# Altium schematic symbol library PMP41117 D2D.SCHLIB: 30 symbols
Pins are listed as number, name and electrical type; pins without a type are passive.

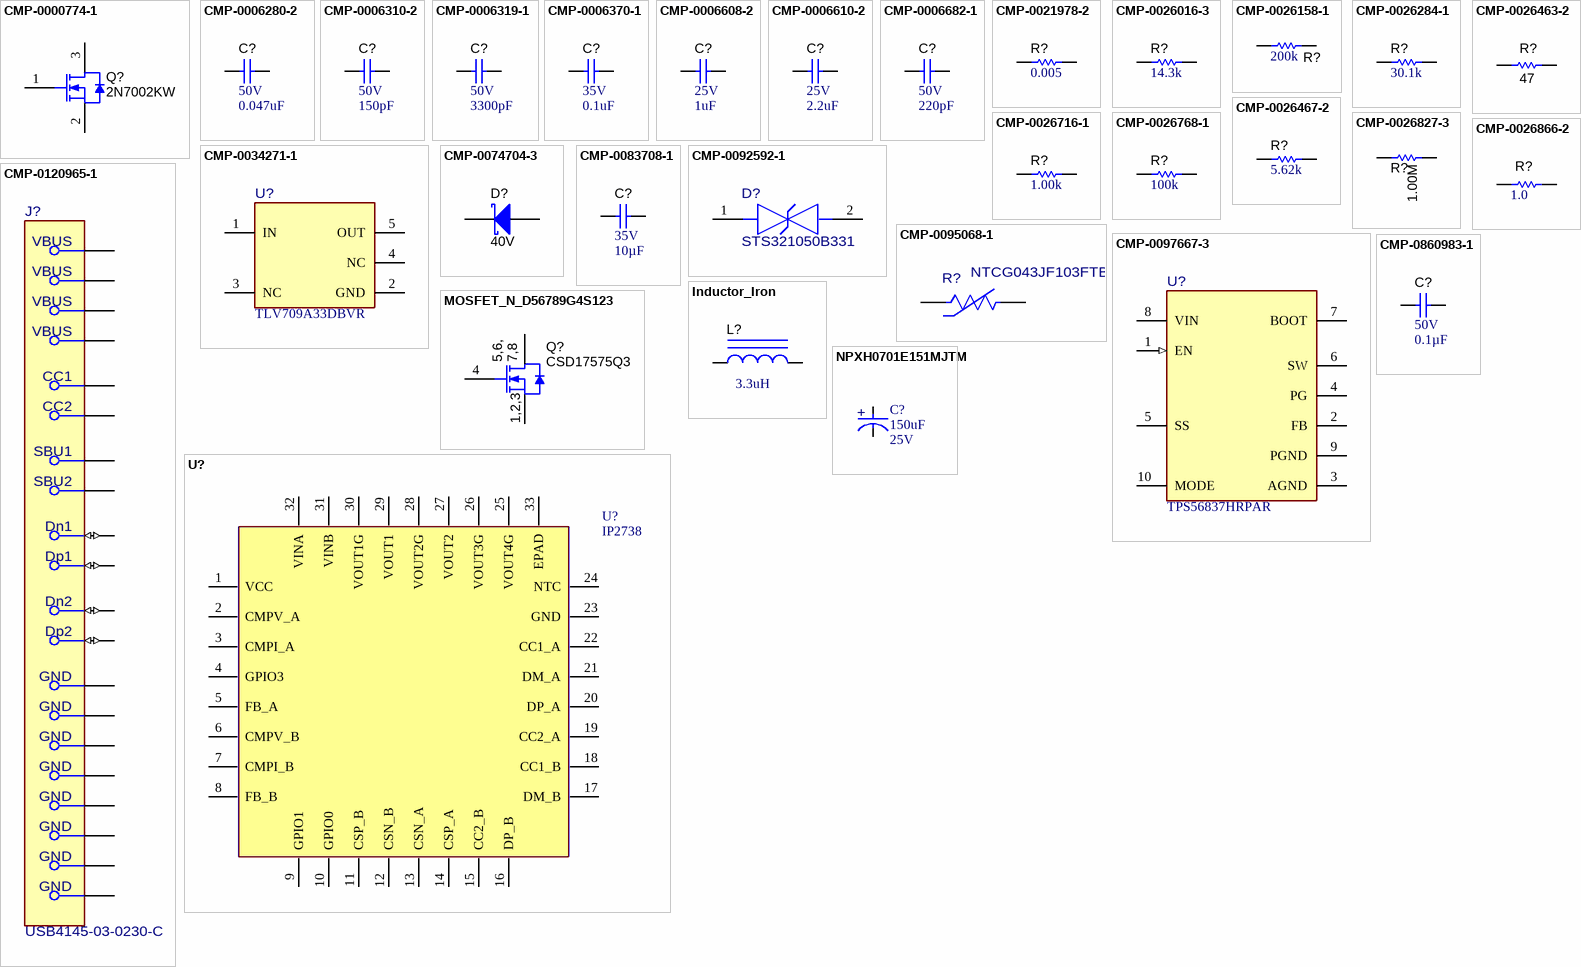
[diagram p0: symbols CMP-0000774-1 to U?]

## CMP-0000774-1
designator Q?, comment 2N7002KW
MOSFET, N-CH, 60 V, 0.31 A, SOT-323; Alternate Manufacturer: None; Manufacturer: Fairchild Semiconductor; SizeZ_mm: 1.1; ChType: N; Value1: 1; VdsMax_V: 60V; SizeX_mm: 2.2; Vgs_V: 2.1V; Value: 60V; Rdson45_ohm: 1.6; SizeArea_mm2: 4.84; AEC Category: Q101; IdsMax_A: 310mA; SizeAreaWB_mm2: 10.24; U/M: EA
footprint SOT-323 (Diodes Inc recommended land pattern.  2016-02-24)
pins: 1 G, 2 S, 3 D

## CMP-0006280-2
designator C?, comment VDC_V: 50V  ValueDisplayed: 0.047uF  (hidden comment: C1005X5R1H473K050BB)
CAP, CERM, 0.047 uF, 50 V, +/- 10%, X5R, 0402; Manufacturer: TDK; TaMin_C: -55°C; ESR_ohm: 64.07m; Polarized: N; SizeAreaWB_mm2: 3; Value1: 0.06407 ohm; U/M: EA; TaMax_C: 85°C; SizeZ_mm: 0.6; SizeX_mm: 1; SizeY_mm: 0.5; Cap_Case: 0402; CompType: Capacitor; Cap_F: 47nF; IRMS_A: 646.122mA; AEC Category: Q200
footprint 0402 (0402 from SM-752 data)
footprint 0402S (Based on C0402S footprint from PADS legacy)
footprint 0402L (0402 from SM-752 data)
footprint 0402M (0402 from SM-752 data)
pins: 1, 2

## CMP-0006310-2
designator C?, comment VDC_V: 50V  ValueDisplayed: 150pF  (hidden comment: CGA2B2C0G1H151J050BA)
CAP, CERM, 150 pF, 50 V, +/- 5%, C0G/NP0, AEC-Q200 Grade 1, 0402; Manufacturer: TDK; TaMin_C: -55°C; Polarized: N; SizeAreaWB_mm2: 3; Value1: Unknown; U/M: EA; Value: 150pF; TaMax_C: 125°C; SizeZ_mm: 0.6; SizeX_mm: 1; SizeY_mm: 0.5; Cap_Case: 0402; CompType: Capacitor; AEC Qualified: Y; AEC Category: Q200
footprint 0402 (0402 from SM-752 data)
footprint 0402S (Based on C0402S footprint from PADS legacy)
footprint 0402L (0402 from SM-752 data)
footprint 0402M (0402 from SM-752 data)
pins: 1, 2

## CMP-0006319-1
designator C?, comment VDC_V: 50V  ValueDisplayed: 3300pF  (hidden comment: CGA2B2X7R1H332K050BA)
CAP, CERM, 3300 pF, 50 V, +/- 10%, X7R, AEC-Q200 Grade 1, 0402; Manufacturer: TDK; TaMin_C: -55°C; ESR_ohm: 0.7852; Polarized: N; SizeAreaWB_mm2: 3; Value1: 0.785178 ohm; U/M: EA; Value: 3300pF; TaMax_C: 125°C; SizeZ_mm: 0.6; SizeX_mm: 1; SizeY_mm: 0.5; Cap_Case: 0402; CompType: Capacitor; AEC Qualified: Y; Cap_F: 3.3nF; IRMS_A: 272.902mA; AEC Category: Q200
footprint 0402 (0402 from SM-752 data)
footprint 0402S (Based on C0402S footprint from PADS legacy)
footprint 0402L (0402 from SM-752 data)
footprint 0402M (0402 from SM-752 data)
pins: 1, 2

## CMP-0006370-1
designator C?, comment VDC_V: 35V  ValueDisplayed: 0.1uF  (hidden comment: GMK105BJ104KV-F)
CAP, CERM, 0.1 uF, 35 V, +/- 10%, X5R, 0402; Manufacturer: Taiyo Yuden; TaMin_C: -55°C; Polarized: N; SizeAreaWB_mm2: 3; Value1: Unknown; U/M: EA; Value: 0.1uF; TaMax_C: 85°C; SizeZ_mm: 0.6; SizeX_mm: 1; SizeY_mm: 0.5; Cap_Case: 0402; CompType: Capacitor; Cap_F: 100nF; AEC Category: Q200
footprint 0402 (0402 from SM-752 data)
footprint 0402S (Based on C0402S footprint from PADS legacy)
footprint 0402L (0402 from SM-752 data)
footprint 0402M (0402 from SM-752 data)
pins: 1, 2

## CMP-0006608-2
designator C?, comment VDC_V: 25V  ValueDisplayed: 1uF  (hidden comment: GRM155R61E105KA12D)
CAP, CERM, 1 uF, 25 V, +/- 10%, X5R, 0402; Manufacturer: MuRata; TaMin_C: -55°C; Polarized: N; SizeAreaWB_mm2: 3; Value1: Unknown; U/M: EA; Value: 1uF; TaMax_C: 85°C; SizeZ_mm: 0.6; SizeX_mm: 1; SizeY_mm: 0.5; Cap_Case: 0402; CompType: Capacitor; Cap_F: 1µF; AEC Category: Q200
footprint 0402 (0402 from SM-752 data)
footprint 0402S (Based on C0402S footprint from PADS legacy)
footprint 0402L (0402 from SM-752 data)
footprint 0402M (0402 from SM-752 data)
pins: 1, 2

## CMP-0006610-2
designator C?, comment VDC_V: 25V  ValueDisplayed: 2.2uF  (hidden comment: GRM155R61E225KE11D)
CAP, CERM, 2.2 uF, 25 V, +/- 10%, X5R, 0402; Manufacturer: MuRata; TaMin_C: -55°C; Polarized: N; SizeAreaWB_mm2: 3; Value1: Unknown; U/M: EA; Value: 2.2uF; TaMax_C: 85°C; SizeZ_mm: 0.7; SizeX_mm: 1; SizeY_mm: 0.5; Cap_Case: 0402; CompType: Capacitor; Cap_F: 2.2µF; AEC Category: Q200
footprint 0402_070 (SMD, 2-Leads, Body 1.2x0.7mm, Height 0.7mm)
pins: 1, 2

## CMP-0006682-1
designator C?, comment VDC_V: 50V  ValueDisplayed: 220pF  (hidden comment: GRM155R71H221KA01D)
CAP, CERM, 220 pF, 50 V, +/- 10%, X7R, 0402; Manufacturer: MuRata; TaMin_C: -55°C; Polarized: N; SizeAreaWB_mm2: 3; Value1: Unknown; U/M: EA; Value: 220pF; TaMax_C: 125°C; SizeZ_mm: 0.6; SizeX_mm: 1; SizeY_mm: 0.5; Cap_Case: 0402; CompType: Capacitor; AEC Category: Q200
footprint 0402 (0402 from SM-752 data)
footprint 0402S (Based on C0402S footprint from PADS legacy)
footprint 0402L (0402 from SM-752 data)
footprint 0402M (0402 from SM-752 data)
pins: 1, 2

## CMP-0021978-2
designator R?, comment ValueDisplayed: 0.005  (hidden comment: WSL08055L000FEA)
RES, 0.005, 1%, 0.25 W, 0805; Manufacturer: Vishay-Dale; Manufacturer: Vishay; Power_W: 250mW; TempCo: 110 ppm/C; Value_Code: 5L000; U/M: EA; Value: 0.005; EIA_Code: E96; Res_ohm: 5m; SizeX_mm: 2.03; SizeY_mm: 1.27; SizeZ_mm: 0.584; Value2: 0.25W; SizeArea_mm2: 2.5781; CompType: Resistor; AEC Qualified: N; AEC Category: Q200
footprint WSL0805 (Vishay)
pins: 1, 2

## CMP-0026016-3
designator R?, comment ValueDisplayed: 14.3k  (hidden comment: CRCW040214K3FKED)
RES, 14.3 k, 1%, 0.063 W, AEC-Q200 Grade 0, 0402; Manufacturer: Vishay-Dale; Manufacturer: Vishay / Dale; Power_W: 63mW; TempCo: 100 ppm/C; Value_Code: 14k3; Value: 14.3k; EIA_Code: E96; SizeX_mm: 1; SizeY_mm: 0.5; SizeZ_mm: 0.6; Value2: 0.063W; CompType: Resistor; AEC Qualified: Y; VDC_V: 50V; AEC Category: Q200; AEC Grade: 0
footprint 0402 (0402 from SM-752 data)
footprint 0402S (Based on C0402S footprint from PADS legacy)
footprint 0402L (0402 from SM-752 data)
footprint 0402M (0402 from SM-752 data)
pins: 1, 2

## CMP-0026158-1
designator R?, comment ValueDisplayed: 200k  (hidden comment: CRCW0402200KFKED)
RES, 200 k, 1%, 0.063 W, 0402; Manufacturer: Vishay-Dale; Power_W: 63mW; TempCo: 100 ppm/C; U/M: EA; Value: 200k; EIA_Code: E96; SizeX_mm: 1; SizeY_mm: 0.5; SizeZ_mm: 0.6; Value2: 0.063W; CompType: Resistor; VDC_V: 50V; AEC Category: Q200
footprint 0402 (0402 from SM-752 data)
footprint 0402S (Based on C0402S footprint from PADS legacy)
footprint 0402L (0402 from SM-752 data)
footprint 0402M (0402 from SM-752 data)
pins: 1, 2

## CMP-0026284-1
designator R?, comment ValueDisplayed: 30.1k  (hidden comment: CRCW040230K1FKED)
RES, 30.1 k, 1%, 0.063 W, 0402; Manufacturer: Vishay-Dale; Power_W: 63mW; TempCo: 100 ppm/C; Value_Code: 30k1; U/M: EA; Value: 30.1k; EIA_Code: E96; SizeX_mm: 1; SizeY_mm: 0.5; SizeZ_mm: 0.6; Value2: 0.063W; CompType: Resistor; VDC_V: 50V; AEC Category: Q200
footprint 0402 (0402 from SM-752 data)
footprint 0402S (Based on C0402S footprint from PADS legacy)
footprint 0402L (0402 from SM-752 data)
footprint 0402M (0402 from SM-752 data)
pins: 1, 2

## CMP-0026463-2
designator R?, comment ValueDisplayed: 47  (hidden comment: CRCW040247R0JNED)
RES, 47, 5%, 0.063 W, 0402; Manufacturer: Vishay-Dale; Power_W: 63mW; TempCo: 200 ppm/C; Value: 47; EIA_Code: E96; SizeX_mm: 1; SizeY_mm: 0.5; SizeZ_mm: 0.6; Value2: 0.063W; CompType: Resistor; AEC Qualified: Y; VDC_V: 50V; AEC Category: Q200; AEC Grade: 0
footprint 0402 (0402 from SM-752 data)
footprint 0402S (Based on C0402S footprint from PADS legacy)
footprint 0402L (0402 from SM-752 data)
footprint 0402M (0402 from SM-752 data)
pins: 1, 2

## CMP-0026467-2
designator R?, comment ValueDisplayed: 5.62k  (hidden comment: CRCW04025K62FKED)
RES, 5.62 k, 1%, 0.063 W, AEC-Q200 Grade 0, 0402; Manufacturer: Vishay-Dale; Power_W: 63mW; TempCo: 100 ppm/C; Value_Code: 5k62; Value: 5.62k; EIA_Code: E96; SizeX_mm: 1; SizeY_mm: 0.5; SizeZ_mm: 0.6; Value2: 0.063W; CompType: Resistor; AEC Qualified: Y; VDC_V: 50V; AEC Category: Q200; AEC Grade: 0
footprint 0402 (0402 from SM-752 data)
footprint 0402S (Based on C0402S footprint from PADS legacy)
footprint 0402L (0402 from SM-752 data)
footprint 0402M (0402 from SM-752 data)
pins: 1, 2

## CMP-0026716-1
designator R?, comment ValueDisplayed: 1.00k  (hidden comment: MCR01MZPF1001)
RES, 1.00 k, 1%, 0.063 W, 0402; Manufacturer: Rohm; Power_W: 63mW; TempCo: 100 ppm/C; Value_Code: 1k00; U/M: EA; Value: 1.00k; EIA_Code: E96; Res_ohm: 1k; SizeX_mm: 1; SizeY_mm: 0.5; SizeZ_mm: 0.6; Value2: 0.063W; CompType: Resistor; AEC Qualified: N; VDC_V: 50V; AEC Category: Q200
footprint 0402 (0402 from SM-752 data)
footprint 0402S (Based on C0402S footprint from PADS legacy)
footprint 0402L (0402 from SM-752 data)
footprint 0402M (0402 from SM-752 data)
pins: 1, 2

## CMP-0026768-1
designator R?, comment ValueDisplayed: 100k  (hidden comment: CRCW0402100KDHEDP)
RES, 100 k, 0.5%, 0.063 W, 0402; Manufacturer: Vishay-Dale; Power_W: 63mW; TempCo: 50 ppm/C; U/M: EA; Value: 100k; EIA_Code: E192; SizeX_mm: 1; SizeY_mm: 0.5; SizeZ_mm: 0.6; Value2: 0.063W; CompType: Resistor; VDC_V: 50V; AEC Category: Q200
footprint 0402 (0402 from SM-752 data)
footprint 0402S (Based on C0402S footprint from PADS legacy)
footprint 0402L (0402 from SM-752 data)
footprint 0402M (0402 from SM-752 data)
pins: 1, 2

## CMP-0026827-3
designator R?, comment ValueDisplayed: 1.00M  (hidden comment: RMCF0402FT1M00)
RES, 1.00 M, 1%, 0.063 W, AEC-Q200 Grade 0, 0402; Manufacturer: Stackpole Electronics Inc; Manufacturer: Vishay / Dale; Manufacturer Part Number: CRCW040210R0JNED; CompType: Resistor; Value: 1.0Meg; Power_W: 63mW; Value2: 0.063W; VDC_V: 50V; TempCo: 200 ppm/C; SizeArea_mm2: 0.5; SizeX_mm: 1; SizeZ_mm: 0.6; EIA_Code: E24; AEC Category: Q200; AEC Qualified: Y; AEC Grade: 0
footprint 0402 (0402 from SM-752 data)
footprint 0402S (Based on C0402S footprint from PADS legacy)
footprint 0402L (0402 from SM-752 data)
footprint 0402M (0402 from SM-752 data)
pins: 1, 2

## CMP-0026866-2
designator R?, comment ValueDisplayed: 1.0  (hidden comment: CRCW04021R00JNED)
RES, 1.0, 5%, 0.063 W, 0402; Manufacturer: Vishay-Dale; Manufacturer: Vishay / Dale; Power_W: 63mW; TempCo: 200 ppm/C; Value_Code: 1R00; U/M: EA; Value: 1.0; EIA_Code: E24; Res_ohm: 1; SizeY_mm: 0.5; SizeZ_mm: 0.6; Value2: 0.063W; CompType: Resistor; VDC_V: 50V; AEC Category: Q200
footprint 0402 (0402 from SM-752 data)
footprint 0402S (Based on C0402S footprint from PADS legacy)
footprint 0402L (0402 from SM-752 data)
footprint 0402M (0402 from SM-752 data)
pins: 1, 2

## CMP-0034271-1
designator U?, comment TLV709A33DBVR
150-mA 30-V low-dropout (LDO) linear regulator with 3.2-μA supply current 5-SOT-23 -40 to 125; Manufacturer: Texas Instruments; SizeZ_mm: 1.45mm; AEC Qualified: No; Accuracy Percentage: 4%; Dropout Voltage: 1000mV; Max Supply Voltage: 30V; Min Supply Voltage: 4.3V; Nominal Supply Current: 3.2uA; Number Of Outputs: 1; Output Type: Fixed; Output Voltage: 3.3V; Standoff Height: 0mm; TJmax_C: +125°C
footprint DBV0005A-MFG
footprint DBV0005A-IPC_C
footprint DBV0005A-IPC_B
footprint DBV0005A-IPC_A
pins: 1 IN (power), 2 GND (power), 3 NC, 4 NC, 5 OUT (power)

## CMP-0074704-3
designator D?, comment value 40V  (hidden comment: RB521SM-40T2R)
Diode, Schottky, 40 V, 0.2 A, SOD-523; Manufacturer: Rohm; SizeAreaWB_mm2: 5.13; SizeZ_mm: 0.65; AEC Category: Q101; AEC Qualified: N; Vf_V: 540mV; Io_A: 200mA; Value2: 0.54V; SizeArea_mm2: 1.53; TJmax_C: 150°C; Value1: 0.2A; SizeX_mm: 1.7; SizeY_mm: 0.9
footprint SOD-523 (NXP Semiconductor recommended land pattern, nominal STEP model)
pins: 1 K, 2 A

## CMP-0083708-1
designator C?, comment VDC_V: 35V  ValueDisplayed: 10µF  (hidden comment: GMK212BBJ106KG-T)
CAP, CERM, 10 µF, 35 V,+/- 10%, X5R, 0805; Manufacturer: Taiyo Yuden; SizeAreaWB_mm2: 6.75; SizeArea_mm2: 2.5; AEC Qualified: N; AEC Category: Q200; Value: 10uF; TaMax_C: 85°C; SizeZ_mm: 1.45; TaMin_C: -55°C; SizeY_mm: 1.25; U/M: EA; CompType: Capacitor; SizeX_mm: 2; Cap_Case: 0805
footprint 0805_HV (0805 with 30mil clearance between pads)
footprint 0805_HV1 (Custom footprint based on analyzing multiple manufacturer recommendations)
footprint 0805 (0805 from SM-752 data)
footprint 0805M (0805 from SM-752 data)
footprint 0805L (0805 from SM-752 data)
pins: 1, 2

## CMP-0092592-1
designator D?, comment STS321050B331
18V Clamp 22A (8/20µs) Ipp Tvs Diode Surface Mount SOD-323; Manufacturer: Eaton; ValueDisplayed: 33pF; Breakdown Voltage: 5.5V; Number Of Channels: 1; SizeZ_mm: 1mm; AEC Qualified: No; Ppk: 400W; VRWM: 5V; TJmax_C: +125°C; Direction: Bidirectional
footprint FP-STS321050B331_SOD-323-MFG
footprint FP-STS321050B331_SOD-323-IPC_C
footprint FP-STS321050B331_SOD-323-IPC_B
footprint FP-STS321050B331_SOD-323-IPC_A
pins: 1, 2

## CMP-0095068-1
designator R?, comment NTCG043JF103FTB
Chip NTC Thermistors (Sensor), Resistance (at 25°C)=10kΩ, Resistance Tolerance (at 25°C)=±1%; Manufacturer: TDK; SizeZ_mm: 0.22mm; B 25 50: 3380K; Value: 10k; B Tolerance: 1%; B 25 100: 3453K; Res_ohm: 10kΩ; B 25 85: 3435K; AEC Qualified: No
footprint FP-NTCG043JF103FTB_SMD2-MFG
footprint FP-NTCG043JF103FTB_SMD2-IPC_C
footprint FP-NTCG043JF103FTB_SMD2-IPC_B
footprint FP-NTCG043JF103FTB_SMD2-IPC_A
pins: 1, 2

## CMP-0097667-3
designator U?, comment TPS56837HRPAR
4.5-V to 28-V Input, 8-A Synchronous Buck Converter; Manufacturer: Texas Instruments; Switching Frequency: 500/800/1200kHz; SizeZ_mm: 1mm; Min Supply Voltage: 4.5V; Nominal Supply Current: 50uA; Output Type: AdjustableProgrammable; AEC Qualified: No; Max Supply Voltage: 28V; Standoff Height: 0mm; Output Voltage: 0.6-13V; TJmax_C: +150°C; Max Duty Cycle: 98%; Number Of Outputs: 1; AEC Category: Q200; CompType: IC
footprint RPA0010A-MFG
pins: 1 EN (in), 2 FB, 3 AGND (power), 4 PG (oc), 5 SS, 6 SW, 7 BOOT, 8 VIN (power), 9 PGND (power), 10 MODE

## CMP-0120965-1
designator J?, comment USB4145-03-0230-C
USB Connectors USB-C Rec 3u Vert 16P SMT 2.3mm TH stakes H7.46mm T+R+Cap; Manufacturer: GCT; Manufacturer: Global Connector Technology; ContactFinish: Gold,Nickel; Current_A: 6.25A; Shrouded: true; Voltage_V: 48V; AEC Qualified: No; Conn Orientation: Vertical; DUT-Pitch_mm: 0.5mm; Is Female: yes; SizeZ_mm: 7.66mm; Standoff Height: 0.05mm; Usb Standard: USB 2.0
footprint FP-USB4145-03-0230-C_CONN_USB-MFG
pins: 1 GND (power), 2 GND (power), 3 GND (power), 4 GND (power), A1 GND (power), A4 VBUS (power), A5 CC1, A6 Dp1 (io), A7 Dn1 (io), A8 SBU1, A9 VBUS (power), A12 GND (power), B1 GND (power), B4 VBUS (power), B5 CC2, B6 Dp2 (io), B7 Dn2 (io), B8 SBU2, B9 VBUS (power), B12 GND (power)

## CMP-0860983-1
designator C?, comment VDC_V: 50V  ValueDisplayed: 0.1µF  (hidden comment: 0402BB104KW500)
CAP, CERM, 0.1 µF, 50 V,+/- 10%, X7R, 0402; Manufacturer: Passive Plus; Cap_Case: 0402; TaMax_C: 125°C; U/M: EA; CompType: Capacitor; SizeY_mm: 0.5; TaMin_C: -55°C; SizeAreaWB_mm2: 3; Value: 0.1uF; AEC Qualified: N; SizeX_mm: 1; AEC Category: Q200; SizeZ_mm: 0.6; Cap_F: 100nF
footprint 0402 (0402 from SM-752 data)
footprint 0402M (0402 from SM-752 data)
footprint 0402L (0402 from SM-752 data)
footprint 0402S (Based on C0402S footprint from PADS legacy)
pins: 1, 2

## Inductor_Iron
designator L?  value 3.3uH
Inductor, Shielded,  3.3 µH, 0.01 ohm, SMD XGL5050-332MEC; Manufacturer: Coilcraft; Ind_H: 5.6µH; SizeY_mm: 6.45; Value2: 6.9A; Irms: 6.9A @ 40C rise; SizeZ_mm: 6.1; SizeX_mm: 6.65; DCR_ohm: 0.0165; Material: Hyperflux; AEC Qualified: N; SizeArea_mm2: 42.8925; AEC Category: Q200; SizeAreaWB_mm2: 73.0925; Isat: 13.6A @ 30% inductance drop; Value1: 0.0165 ohm; Parameter 3: 5mm*5mm*5mm
footprint WE-XHMI_6060 (SMD, 2-Leads, Body 6.65x6.45mm)
pins: 1, 2

## MOSFET_N_D56789G4S123
designator Q?, comment CSD17575Q3
MOSFET, N-CH, 30 V, 60 A, DQG0008A (VSON-CLIP-8); Manufacturer: Texas Instruments; Alternate Manufacturer: None; U/M: EA; ChType: N; Value: 30V; Value1: 0.003; Rdson45_ohm: 3.2m; Value2: 23 nC; QgTyp_nC: 23; Vgs_V: 20V; IdsMax_A: 60A; AEC Category: Q101; SizeZ_mm: 1.1; SizeX_mm: 3.3; SizeArea_mm2: 10.89; SizeAreaWB_mm2: 18.49
footprint DQG0008A (SMD, 8-Leads, Body 3.3x3.3mm, Pitch 0.65mm)
footprint DQG0008A_NV (SMD, 8-Leads, Body 3.3x3.3mm, Pitch 0.65mm)
pins: 1 S, 2 S, 3 S, 4 G, 5 D, 6 D, 7 D, 8 D, 9 D

## NPXH0701E151MJTM
designator C?, comment value 150uF  Voltage: 25V  (hidden comment: CAP 25V 150uF D 5.5X7mm)
PartNumber: NPXH0701E151MJTM; Manufacturer: Yongming
footprint Ecap_5.5_9_2.5
pins: 1 CATHODE, 2 ANODE

## U?
designator U?, comment IP2738
IP2738 dual port USB PD controller
footprint IP2738
pins: 1 VCC, 2 CMPV_A, 3 CMPI_A, 4 GPIO3, 5 FB_A, 6 CMPV_B, 7 CMPI_B, 8 FB_B, 9 GPIO1, 10 GPIO0, 11 CSP_B, 12 CSN_B, 13 CSN_A, 14 CSP_A, 15 CC2_B, 16 DP_B, 17 DM_B, 18 CC1_B, 19 CC2_A, 20 DP_A, 21 DM_A, 22 CC1_A, 23 GND, 24 NTC, 25 VOUT4G, 26 VOUT3G, 27 VOUT2, 28 VOUT2G, 29 VOUT1, 30 VOUT1G, 31 VINB, 32 VINA, 33 EPAD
